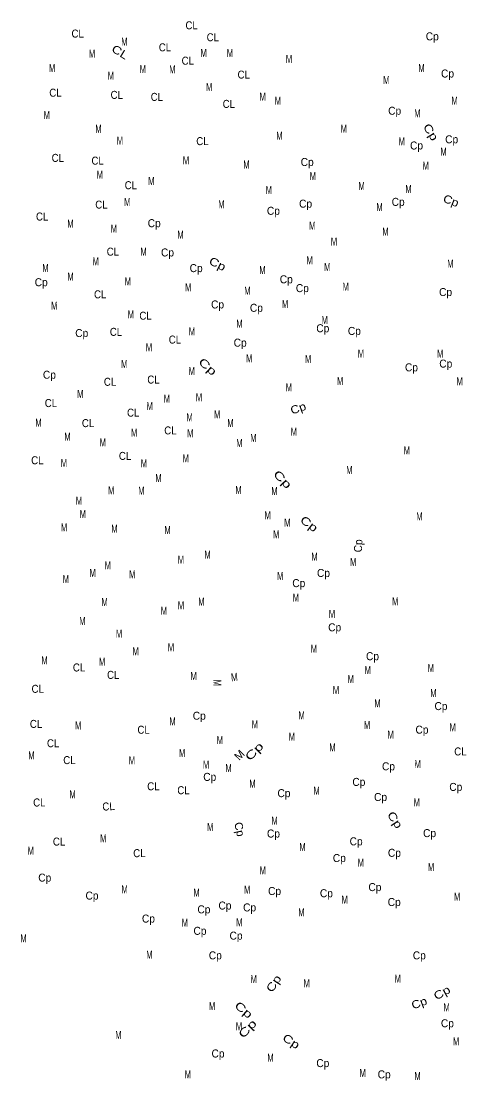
# Model space of a CAD drawing. Extents: x 713577 to 726626, y 7177731 to 7191794.
# Drawn here: x 717167 to 719267, y 7177882 to 7182911 of the extents above; entities that cross this region are included whole.
import ezdxf
from ezdxf.enums import TextEntityAlignment as Align

# ---------------------------------------------------------------- set-up
doc = ezdxf.new("R2010")
doc.units = 0
doc.header["$LTSCALE"] = 15
doc.layers.add('19', color=7, linetype='Continuous')

msp = doc.modelspace()

# ---------------------------------------------------------------- texts
at = {"layer": '19'}
for s, rotation, width, p in [('CL', 359.99, 0.9, (717975.24, 7182872.06)), ('CL', 359.99, 0.9, (717434.56, 7182832.9)), ('M', 359.99, 0.65, (717656.3, 7182794.39)), ('CL', 359.99, 0.9, (718075.85, 7182815.3)), ('Cp', 359.99, 0.95, (719117.26, 7182819.69)), ('CL', 328.308, 1.25, (717625.87, 7182748.05)), ('CL', 359.99, 0.9, (717848.88, 7182767.51)), ('M', 359.99, 0.65, (718032.35, 7182740.89)), ('M', 359.99, 0.65, (718157.05, 7182740.2)), ('M', 359.99, 0.65, (717502.9, 7182737.68)), ('CL', 359.99, 0.9, (717957.07, 7182704.15)), ('M', 359.99, 0.65, (718437.45, 7182712.47)), ('M', 359.99, 0.65, (717313.36, 7182669.08)), ('M', 359.99, 0.65, (717743.7, 7182664.4)), ('M', 359.99, 0.65, (717883.89, 7182663.06)), ('CL', 359.99, 0.9, (718222.61, 7182638.13)), ('M', 359.99, 0.65, (719066.3, 7182669.59)), ('Cp', 359.99, 0.95, (719189.63, 7182643.3)), ('M', 359.99, 0.65, (717592.08, 7182633.17)), ('M', 359.99, 0.65, (718899.05, 7182611.76)), ('CL', 359.99, 0.9, (717329.13, 7182552.26)), ('CL', 359.99, 0.9, (717620.03, 7182542.01)), ('M', 359.99, 0.65, (718058.69, 7182579.77)), ('CL', 359.99, 0.9, (717810.36, 7182532.43)), ('CL', 359.99, 0.9, (718151.93, 7182499.14)), ('M', 359.99, 0.65, (718312.39, 7182533)), ('M', 359.99, 0.65, (718384.63, 7182513.87)), ('M', 359.99, 0.65, (719223.24, 7182514.57)), ('M', 359.99, 0.65, (717287.98, 7182446.31)), ('Cp', 359.99, 0.95, (718938.84, 7182466.63)), ('M', 359.99, 0.65, (719046.51, 7182455.03)), ('M', 359.99, 0.65, (717533.13, 7182380.78)), ('M', 359.99, 0.65, (718391.85, 7182347.61)), ('M', 359.99, 0.65, (718697.36, 7182381.38)), ('Cp', 302.148, 1.3, (719093.95, 7182374.23)), ('M', 359.99, 0.65, (717635.13, 7182325.15)), ('CL', 359.99, 0.9, (718026.53, 7182322.45)), ('M', 359.99, 0.65, (718972.38, 7182321.18)), ('Cp', 359.99, 0.95, (719042.47, 7182301.75)), ('Cp', 359.99, 0.95, (719209.32, 7182331.01)), ('CL', 359.99, 0.9, (717340.4, 7182242.93)), ('M', 359.99, 0.65, (719170.8, 7182272.77)), ('CL', 359.99, 0.9, (717529.28, 7182229.74)), ('M', 359.99, 0.65, (717948.72, 7182230.65)), ('M', 359.99, 0.65, (718235.33, 7182211.51)), ('Cp', 359.99, 0.95, (718523.63, 7182223.46)), ('M', 359.99, 0.65, (719086.22, 7182205.98)), ('M', 359.99, 0.65, (717539.67, 7182163.92)), ('M', 359.99, 0.65, (718550.55, 7182156.65)), ('CL', 359.99, 0.9, (717686.89, 7182113.22)), ('M', 359.99, 0.65, (717784.16, 7182132.62)), ('M', 359.99, 0.65, (718341.62, 7182091.2)), ('M', 359.99, 0.65, (718781.92, 7182109.22)), ('M', 359.99, 0.65, (719004.26, 7182095.43)), ('Cp', 359.99, 0.95, (718955.29, 7182034.17)), ('Cp', 338.694, 1.15, (719199.45, 7182040.96)), ('CL', 359.99, 0.9, (717547.35, 7182021.1)), ('M', 359.99, 0.65, (717669.96, 7182033.59)), ('M', 359.99, 0.65, (718116.53, 7182023.12)), ('Cp', 359.99, 0.95, (718363.33, 7181991.82)), ('Cp', 359.99, 0.95, (718516.03, 7182025.69)), ('M', 359.99, 0.65, (718867.03, 7182009.24)), ('CL', 359.99, 0.9, (717265.98, 7181964.55)), ('M', 359.99, 0.65, (717400.24, 7181930.63)), ('M', 359.99, 0.65, (717606.43, 7181907.56)), ('Cp', 359.99, 0.95, (717797.64, 7181933.01)), ('M', 359.99, 0.65, (718547.88, 7181920.71)), ('M', 359.99, 0.65, (718895.11, 7181893.2)), ('M', 359.99, 0.65, (717922.68, 7181878.37)), ('M', 359.99, 0.65, (718650.86, 7181845.99)), ('CL', 359.99, 0.9, (717601.6, 7181797.98)), ('M', 359.99, 0.65, (717747.27, 7181797.77)), ('Cp', 359.99, 0.95, (717860.8, 7181794.13)), ('M', 359.99, 0.65, (717520.31, 7181752.59)), ('Cp', 332.732, 1.25, (718089.49, 7181742.04)), ('M', 359.99, 0.65, (718535.39, 7181756.83)), ('M', 359.99, 0.65, (719203.09, 7181740.79)), ('M', 359.99, 0.65, (717281.73, 7181720.71)), ('Cp', 359.99, 0.95, (717996.69, 7181719.74)), ('M', 359.99, 0.65, (718311.28, 7181710.47)), ('M', 359.99, 0.65, (718618.99, 7181724.31)), ('Cp', 359.99, 0.95, (717261.54, 7181652.74)), ('M', 359.99, 0.65, (717400.85, 7181679.88)), ('M', 359.99, 0.65, (717672.66, 7181656.47)), ('Cp', 359.99, 0.95, (718424.48, 7181666.69)), ('CL', 359.99, 0.9, (717541.35, 7181595.29)), ('M', 359.99, 0.65, (717959.16, 7181628.92)), ('M', 359.99, 0.65, (718239.86, 7181612.09)), ('Cp', 359.99, 0.95, (718500.77, 7181624.88)), ('M', 359.99, 0.65, (718706.5, 7181631.3)), ('Cp', 359.99, 0.95, (719180.36, 7181606.07)), ('M', 359.99, 0.65, (717323.49, 7181541.03)), ('Cp', 359.99, 0.95, (718098.35, 7181547.29)), ('Cp', 359.99, 0.95, (718282.62, 7181531.46)), ('M', 359.99, 0.65, (718418.86, 7181549.54)), ('M', 359.99, 0.65, (717686.78, 7181500.16)), ('CL', 359.99, 0.9, (717756.54, 7181493.89)), ('M', 359.99, 0.65, (718202.32, 7181455.79)), ('Cp', 359.99, 0.95, (718597.81, 7181434.33)), ('M', 359.99, 0.65, (718606.77, 7181473.03)), ('Cp', 359.99, 0.95, (717453.87, 7181411.63)), ('CL', 359.99, 0.9, (717616.34, 7181417.25)), ('CL', 359.99, 0.9, (717896.05, 7181380.67)), ('M', 359.99, 0.65, (717976.68, 7181419.16)), ('Cp', 359.99, 0.95, (718747.6, 7181421.54)), ('M', 359.99, 0.65, (717772.97, 7181343.84)), ('Cp', 359.99, 0.95, (718205.59, 7181365.95)), ('M', 359.99, 0.65, (718248.71, 7181291.97)), ('M', 359.99, 0.65, (718778.84, 7181314.06)), ('M', 359.99, 0.65, (719154.84, 7181313.53)), ('M', 359.99, 0.65, (717655.81, 7181264.22)), ('M', 359.99, 0.65, (717975.88, 7181231.4)), ('Cp', 317.571, 1.45, (718038.72, 7181257.23)), ('Cp', 359.99, 0.95, (719018.4, 7181248.73)), ('Cp', 359.99, 0.95, (719181.29, 7181266.47)), ('Cp', 359.99, 0.95, (717300.49, 7181213.88)), ('CL', 359.99, 0.9, (717588.09, 7181180.27)), ('CL', 359.99, 0.9, (717794.33, 7181190.81)), ('M', 359.99, 0.65, (718680.1, 7181184.09)), ('M', 359.99, 0.65, (719247.29, 7181182.22)), ('M', 359.99, 0.65, (718436.58, 7181154.19)), ('CL', 359.99, 0.9, (717307.71, 7181079.29)), ('M', 359.99, 0.65, (717447.15, 7181122.76)), ('M', 359.99, 0.65, (717857.83, 7181099.98)), ('M', 359.99, 0.65, (718010.41, 7181106.68)), ('CL', 359.99, 0.9, (717697.97, 7181033.81)), ('M', 359.99, 0.65, (717776.54, 7181064.78)), ('Cp', 19.553, 1.15, (718487.12, 7181055.85)), ('M', 359.99, 0.65, (717248.76, 7180986.16)), ('CL', 359.99, 0.9, (717483.74, 7180984.16)), ('M', 359.99, 0.65, (717965.75, 7181011.77)), ('M', 359.99, 0.65, (718096.63, 7181025.45)), ('M', 359.99, 0.65, (718159.47, 7180983.98)), ('M', 359.99, 0.65, (717702.81, 7180939.09)), ('CL', 359.99, 0.9, (717874.67, 7180949.54)), ('M', 359.99, 0.65, (717969.02, 7180936.08)), ('M', 359.99, 0.65, (718460.24, 7180942.92)), ('M', 359.99, 0.65, (717386.24, 7180920.06)), ('M', 359.99, 0.65, (717553.73, 7180892.39)), ('M', 359.99, 0.65, (718201.91, 7180889.2)), ('M', 359.99, 0.65, (718268.39, 7180914.2)), ('CL', 359.99, 0.9, (717659.44, 7180828.48)), ('M', 359.99, 0.65, (718996.61, 7180854.64)), ('CL', 359.905, 0.9, (717243.13, 7180807.78)), ('M', 359.99, 0.65, (717369.5, 7180794.62)), ('M', 359.99, 0.65, (717748.85, 7180793.96)), ('M', 359.99, 0.65, (717947.52, 7180817.5)), ('Cp', 314.009, 1.5, (718393.14, 7180722.94)), ('M', 359.99, 0.65, (718723.79, 7180760.9)), ('M', 359.99, 0.65, (717817.94, 7180723.2)), ('M', 359.99, 0.65, (717593.9, 7180664.93)), ('M', 359.99, 0.65, (717736.89, 7180663.21)), ('M', 359.99, 0.65, (718197.59, 7180667.4)), ('M', 359.99, 0.65, (718368.31, 7180661.71)), ('M', 359.99, 0.65, (717440.55, 7180615.92)), ('M', 359.99, 0.65, (717458.96, 7180553.07)), ('M', 359.99, 0.65, (718336.04, 7180547.2)), ('M', 359.99, 0.65, (719056.11, 7180541.35)), ('M', 359.99, 0.65, (717370.12, 7180488.93)), ('M', 359.99, 0.65, (717609.18, 7180482.9)), ('M', 359.99, 0.65, (717861.18, 7180476.87)), ('M', 359.99, 0.65, (718429.56, 7180511.19)), ('Cp', 323.24, 1.35, (718521.36, 7180509.94)), ('M', 359.99, 0.65, (718376.83, 7180456.7)), ('Cp', 87.041, 0.95, (718784.53, 7180419.76)), ('M', 359.99, 0.65, (717924.67, 7180336.01)), ('M', 359.99, 0.65, (718051.04, 7180360.34)), ('M', 359.99, 0.65, (718558.53, 7180350.25)), ('M', 359.99, 0.65, (718742.14, 7180325.21)), ('M', 359.99, 0.65, (717577.41, 7180309.22)), ('M', 359.99, 0.65, (717378.64, 7180244.1)), ('M', 359.99, 0.65, (717505.66, 7180273.37)), ('M', 359.99, 0.65, (717693.59, 7180266.53)), ('M', 359.99, 0.65, (718395.88, 7180259.26)), ('Cp', 359.99, 0.95, (718483.81, 7180224.75)), ('Cp', 359.99, 0.95, (718600.96, 7180272.91)), ('M', 359.99, 0.65, (717562.42, 7180134.45)), ('M', 359.99, 0.65, (718021.71, 7180136.91)), ('M', 359.99, 0.65, (718469.97, 7180156.11)), ('M', 359.99, 0.65, (718941.53, 7180138.13)), ('M', 359.99, 0.65, (717843.72, 7180093.54)), ('M', 359.99, 0.65, (717924.96, 7180118.83)), ('M', 359.99, 0.65, (718641.4, 7180078.75)), ('M', 359.99, 0.65, (717456.91, 7180045.14)), ('M', 359.99, 0.65, (717630.82, 7179984.28)), ('Cp', 359.99, 0.95, (718654.23, 7180014.91)), ('M', 359.99, 0.65, (717709.68, 7179901.59)), ('M', 359.99, 0.65, (717877.27, 7179920.56)), ('M', 359.99, 0.65, (718555.49, 7179913.24)), ('Cp', 359.99, 0.95, (718833.55, 7179877.98)), ('M', 359.99, 0.65, (717277.26, 7179858.58)), ('CL', 359.99, 0.9, (717441.09, 7179824.53)), ('M', 359.99, 0.65, (717550.64, 7179851.24)), ('M', 359.99, 0.65, (719110.61, 7179821.99)), ('CL', 359.99, 0.9, (717603.28, 7179789.33)), ('M', 359.99, 0.65, (717984.95, 7179783.37)), ('M', 4.832, 0.75, (718179.56, 7179779.12)), ('M', 359.99, 0.65, (718811.16, 7179811.84)), ('CL', 359.99, 0.9, (717244.98, 7179723.19)), ('M', 270, 0.65, (718078.71, 7179770.68)), ('M', 359.99, 0.65, (718730.46, 7179769.21)), ('M', 359.99, 0.65, (718660.43, 7179716.77)), ('M', 359.99, 0.65, (719122.64, 7179702.74)), ('M', 359.99, 0.65, (718857.2, 7179654.54)), ('Cp', 359.99, 0.95, (719158.5, 7179641.19)), ('Cp', 359.99, 0.95, (718011.59, 7179595.39)), ('M', 359.99, 0.65, (718497.19, 7179596.69)), ('CL', 359.99, 0.9, (717237.03, 7179556.56)), ('M', 359.99, 0.65, (717437.18, 7179549.05)), ('CL', 359.99, 0.9, (717747.38, 7179528.91)), ('M', 359.99, 0.65, (717884.81, 7179568.61)), ('M', 359.99, 0.65, (718275.39, 7179554.8)), ('M', 359.99, 0.65, (718807.82, 7179551.88)), ('Cp', 359.99, 0.95, (719068.31, 7179529.33)), ('M', 359.99, 0.65, (719214.09, 7179540.82)), ('M', 359.99, 0.65, (718109.4, 7179479.55)), ('M', 359.99, 0.65, (718450.77, 7179496)), ('M', 359.99, 0.65, (718919.9, 7179505.66)), ('CL', 359.99, 0.9, (717318.12, 7179464.67)), ('Cp', 45, 1.5, (718285.7, 7179431.66)), ('M', 359.99, 0.65, (718643.6, 7179444.96)), ('CL', 359.99, 0.9, (719250.6, 7179425.96)), ('M', 359.99, 0.65, (717215.09, 7179407.48)), ('CL', 359.99, 0.9, (717395.4, 7179384.83)), ('M', 359.99, 0.65, (717692.17, 7179383.32)), ('M', 359.99, 0.65, (717930.4, 7179418.76)), ('M', 359.99, 0.65, (718043.8, 7179363.62)), ('M', 359.99, 0.65, (718150.55, 7179346.81)), ('Cp', 359.99, 0.95, (718909.34, 7179355.27)), ('M', 359.99, 0.65, (719048.21, 7179366.11)), ('Cp', 359.99, 0.95, (718061.28, 7179305.2)), ('M', 359.99, 0.65, (718263.88, 7179272.32)), ('Cp', 359.99, 0.95, (718768.81, 7179281.26)), ('M', 359.99, 0.65, (717410.51, 7179222.44)), ('CL', 359.99, 0.9, (717793.89, 7179260.43)), ('CL', 359.99, 0.9, (717936.77, 7179241.86)), ('Cp', 359.99, 0.95, (718413.4, 7179227.95)), ('M', 359.99, 0.65, (718568.31, 7179239.96)), ('Cp', 359.99, 0.95, (719228.85, 7179257.48)), ('CL', 359.99, 0.9, (717252.49, 7179183.69)), ('Cp', 359.99, 0.95, (718871.8, 7179209.5)), ('M', 359.99, 0.65, (719043.57, 7179184.13)), ('CL', 3.663, 0.9, (717582.15, 7179165.37)), ('Cp', 303.671, 1.3, (718924.51, 7179109.69)), ('Cp', 282.197, 1.05, (718184.48, 7179071.58)), ('M', 359.99, 0.65, (718369.03, 7179097.75)), ('M', 359.99, 0.65, (718063.71, 7179067.1)), ('Cp', 359.99, 0.95, (718363.63, 7179036.3)), ('Cp', 359.99, 0.95, (719104.42, 7179038.35)), ('CL', 359.99, 0.9, (717346.23, 7178998.04)), ('M', 359.99, 0.65, (717555.95, 7179013.52)), ('M', 359.99, 0.65, (718501.42, 7178972.92)), ('Cp', 359.99, 0.95, (718755.81, 7178999.16)), ('M', 359.99, 0.65, (717211.9, 7178954.66)), ('CL', 359.99, 0.9, (717727.32, 7178943.17)), ('Cp', 359.99, 0.95, (718676.28, 7178919.98)), ('Cp', 359.99, 0.95, (718937.57, 7178944.92)), ('M', 359.99, 0.65, (718777.97, 7178898.74)), ('M', 359.99, 0.65, (719111.63, 7178877.1)), ('Cp', 359.99, 0.95, (717278.41, 7178826.98)), ('M', 359.99, 0.65, (718312.92, 7178861.44)), ('M', 359.99, 0.65, (717657.28, 7178771.8)), ('M', 359.99, 0.65, (718239.09, 7178770.22)), ('Cp', 359.99, 0.95, (718845.11, 7178782.15)), ('Cp', 359.99, 0.95, (717502.68, 7178741.73)), ('M', 359.99, 0.65, (717998.71, 7178756.34)), ('Cp', 359.99, 0.95, (718368.97, 7178763.54)), ('Cp', 359.99, 0.95, (718614.8, 7178753.04)), ('M', 359.99, 0.65, (718701.59, 7178721.98)), ('M', 359.99, 0.65, (719235.34, 7178736.24)), ('Cp', 359.99, 0.95, (718033.6, 7178676.38)), ('Cp', 359.99, 0.95, (718133.47, 7178694.61)), ('Cp', 359.99, 0.95, (718250.48, 7178685.63)), ('Cp', 359.99, 0.95, (718936.65, 7178711.17)), ('Cp', 359.99, 0.95, (717770.35, 7178632.71)), ('M', 359.99, 0.65, (718201.68, 7178615)), ('M', 359.99, 0.65, (718496.3, 7178663.1)), ('M', 359.99, 0.65, (717943.31, 7178613.35)), ('Cp', 359.99, 0.95, (718014.9, 7178574.69)), ('M', 359.99, 0.65, (717177.62, 7178539.36)), ('Cp', 359.99, 0.95, (718186.14, 7178551.64)), ('M', 359.99, 0.65, (717774.75, 7178461.01)), ('Cp', 359.99, 0.95, (718087.74, 7178458.1)), ('Cp', 359.99, 0.95, (719055.72, 7178458.04)), ('M', 359.99, 0.65, (718270.06, 7178345.4)), ('Cp', 57.25, 1.3, (718380.7, 7178333.02)), ('M', 359.99, 0.65, (718521.27, 7178326.03)), ('M', 359.99, 0.65, (718953.37, 7178348.13)), ('Cp', 29.162, 1.25, (719172.4, 7178283.12)), ('M', 359.99, 0.65, (718072.49, 7178217.03)), ('Cp', 319.751, 1.4, (718210.15, 7178203.92)), ('Cp', 20.548, 1.15, (719061.72, 7178233.34)), ('M', 359.99, 0.65, (719185.24, 7178211.87)), ('M', 359.99, 0.65, (718200.01, 7178121.44)), ('Cp', 46.436, 1.5, (718254.09, 7178115.72)), ('Cp', 359.99, 0.95, (719189.03, 7178135.84)), ('M', 359.99, 0.65, (717627.69, 7178080.57)), ('Cp', 326.456, 1.3, (718437.58, 7178053.61)), ('M', 359.99, 0.65, (719230.19, 7178049.98)), ('Cp', 359.99, 0.95, (718100.64, 7177992.42)), ('M', 359.99, 0.65, (718349.51, 7177971.89)), ('Cp', 359.99, 0.95, (718597.86, 7177946.82)), ('M', 359.99, 0.65, (717957.44, 7177893.29)), ('M', 359.99, 0.65, (718786.98, 7177899.27)), ('Cp', 359.99, 0.95, (718888.98, 7177893.23)), ('M', 359.99, 0.65, (719047.38, 7177885.6))]:
    msp.add_text(s, height=38, rotation=rotation, dxfattribs=dict(at, width=width)).set_placement(p, align=Align.CENTER)
at = {"layer": '19', "width": 0.65}
msp.add_text('M', height=38, dxfattribs=at).set_placement((718528.41, 7181289.09), align=Align.CENTER)
at = {"layer": '19'}
msp.add_text('M', height=38, rotation=45.909, dxfattribs=at).set_placement((718215.71, 7179414.74), align=Align.CENTER)

doc.saveas('drawing.dxf')
